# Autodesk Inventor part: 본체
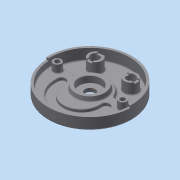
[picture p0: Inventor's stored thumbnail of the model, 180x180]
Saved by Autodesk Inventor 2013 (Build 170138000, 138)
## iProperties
Created: 2015-04
Part Number: 본체
Material: 일반
Document SubType Name: Modeling
Designer: Administrator
Density: 1 g/cm^3
Author: Administrator
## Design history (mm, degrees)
sketch "스케치1"
  geometry: C1 r 95 at (0, 0); 1 further point
  constraints: 1 centre point, 1 coincident
  dimensions: "d0" = 190 diameter of C1
extrude "돌출1" new body sketch "스케치1" distance "d1" = 32; taper "d2" = 0 deg
sketch "스케치2"
  geometry: C1 r 95 at (0, 0) reference; C2 r 90 at (0, 0)
  constraints: 1 centre point, 1 coincident
  dimensions: "d3" = 180 diameter of C2
extrude "돌출2" cut sketch "스케치2" distance "d4" = 25; taper "d5" = 0 deg
sketch "스케치3"
  geometry: L1 (-101.472, 0)-(101.472, 0); L2 (-94.916, -4)-(-89.929, -3.564); L3 (89.951, -2.955)-(94.939, -3.391); C1 r 90 at (0, 0) reference; A1 r 95 centre (0, 0) between (-95, 0) and (95, 0); A2 r 90 centre (0, 0) between (-90, 0) and (90, 0); 1 further point
  constraints: 8 point on circle, 6 end point, 4 point on line, 3 coincident, 2 centre point, 1 horizontal, 1 midpoint
  dimensions: "d6" = 5 deg angle of L2 L1; "d7" = 190 diameter of A1; "d8" = 180 diameter of A2; "d9" = 4.98634 horizontal distance of L2.start L2.end; "d10" = 5 deg angle of L1 L3; "d11" = 4.98797 horizontal distance of L3.start L3.end
extrude "돌출3" cut sketch "스케치3" distance "d12" = 5; taper "d13" = 0 deg
node "작업 평면1"
sketch "스케치9"
  geometry: C1 r 15 at (-40, 52); C2 r 15 at (40, 52); 1 further point
  constraints: 2 centre point, 1 horizontal alignment
  dimensions: "d77" = 30 diameter of C1; "d78" = 30 diameter of C2; "d79" = 80 distance of C2.centre C1.centre; "d80" = 40 horizontal distance of point (0, 0) C1.centre; "d81" = 52 vertical distance of point (0, 0) C1.centre
extrude "돌출7" join sketch "스케치9" stored distance "d82" = 25; taper "d83" = 0 deg
sketch "스케치10"
  geometry: C1 r 15 at (0, 0) reference; C2 r 15 at (80, 0) reference; C3 r 10 at (0, 0); C4 r 10 at (80, 0); 1 further point
  constraints: 2 centre point, 2 coincident
  dimensions: "d84" = 20 diameter of C3; "d85" = 20 diameter of C4
extrude "돌출8" cut sketch "스케치10" stored distance "d86" = 25; taper "d87" = 0 deg
sketch "스케치11"
  geometry: L1 (-6, 19.341)-(6, 19.341); L2 (6, 19.341)-(6, -18.609); L3 (6, -18.609)-(-6, -18.609); L4 (-6, -18.609)-(-6, 19.341); L5 (59.177, 6)-(102.733, 6); L6 (102.733, 6)-(102.733, -6); L7 (102.733, -6)-(59.177, -6); L8 (59.177, -6)-(59.177, 6); C1 r 10 at (0, 0) reference; C2 r 10 at (80, 0) reference; C3 r 15 at (80, 0) reference; 3 further points
  constraints: 16 end point, 4 parallel, 2 horizontal, 2 midpoint, 2 perpendicular, 1 horizontal alignment, 1 vertical alignment
  dimensions: "d88" = 12 distance of L1.start L1.end; "d90" = 12 distance of L7.end L5.start
extrude "돌출9" cut sketch "스케치11" distance "d92" = 3; taper "d93" = 0 deg
sketch "스케치12"
  geometry: L1 (-89.196, 12)-(-40.249, 12); L2 (40.249, 12)-(89.196, 12); A1 r 90 centre (0, 0) between (-89.196, 12) and (89.196, 12) reference; A2 r 42 centre (0, 0) between (40.249, 12) and (-40.249, 12); A3 r 90 centre (0, 0) between (-89.196, 12) and (89.196, 12)
  constraints: 6 point on circle, 4 end point, 2 centre point, 2 coincident, 2 horizontal, 1 horizontal alignment
  dimensions: "d98" = 12 distance from line of A1.centre L2; "d100" = 42 radius of A2
extrude "돌출10" join sketch "스케치12" distance "d101" = 7; taper "d102" = 0 deg
sketch "스케치13"
  geometry: A1 r 90 centre (0, 0) between (-89.196, 12) and (89.196, 12) reference; A2 r 59 centre (0, -19) between (-58.704, -13.1) and (58.704, -13.1); A3 r 41 centre (0, -19) between (-40.794, -14.9) and (40.794, -14.9); A4 r 9 centre (-49.749, -14) between (-40.794, -14.9) and (-58.704, -13.1); A5 r 9 centre (49.749, -14) between (58.704, -13.1) and (40.794, -14.9)
  constraints: 8 point on circle, 4 centre point, 2 tangent, 1 coincident, 1 horizontal alignment, 1 vertical alignment
  dimensions: "d103" = 118 diameter of A2; "d104" = 19 distance of A2.centre A1.centre; "d105" = 82 diameter of A3; "d106" = 18 diameter of A4; "d107" = 18 diameter of A5; "d108" = 5 vertical distance of A4.centre A3.centre
extrude "돌출11" cut sketch "스케치13" distance "d109" = 7; taper "d110" = 0 deg
sketch "스케치14"
  geometry: C1 r 9 at (-74, 0); C2 r 9 at (74, 0); A1 r 90 centre (0, 0) between (-89.196, 12) and (89.196, 12) reference
  constraints: 2 centre point, 2 horizontal alignment
  dimensions: "d111" = 18 diameter of C1; "d112" = 18 diameter of C2; "d113" = 148 distance of C2.centre C1.centre; "d114" = 74 distance of A1.centre C1.centre
extrude "돌출12" join sketch "스케치14" stored distance "d115" = 7; taper "d116" = 0 deg
sketch "스케치15"
  geometry: C1 r 9 at (-74, 0) reference; C2 r 9 at (74, 0) reference; 2 further points
  constraints: 2 coincident
hole "구멍5" sketch "스케치15" at (-74, 0), (74, 0) diameter "d117" = 11; stored, may be unused: countersink angle "d121" = 90 deg, drill point angle "d123" = 0 deg; dims "d118" = 6, "d119" = 18, "d120" = 11, "d122" = 11
sketch "스케치16"
  geometry: C1 r 35 at (0, 0); A1 r 42 centre (0, 0) between (40.249, 12) and (-40.249, 12) reference
  constraints: 1 centre point, 1 coincident
  dimensions: "d124" = 70 diameter of C1
extrude "돌출13" join sketch "스케치16" distance "d125" = 10; taper "d126" = -10 deg
hole "구멍6" diameter "d129" = 23; stored, may be unused: countersink angle "d133" = 90 deg, drill point angle "d135" = 0 deg; dims "d127" = 10, "d128" = 10, "d130" = 6, "d131" = 50, "d132" = 15, "d134" = 11
fillet "모깎기4" dims "d136" = 10
fillet "모깎기5" dims "d137" = 3, "d159" = 1
chamfer "모따기1" distance "d138" = 1; stored, may be unused: second distance "d139" = 2, angle "d140" = 45 deg
sketch "스케치17"
  geometry: L1 (-40, 0)-(43.953, 0); L2 (-36.062, -36.062)-(-52.326, -52.326); L3 (36.062, -36.062)-(52.326, -52.326); C1 r 12.5 at (0, 0) reference; A1 r 51 centre (0, 0) between (-36.062, -36.062) and (36.062, -36.062); A2 r 74 centre (0, 0) between (-52.326, -52.326) and (52.326, -52.326)
  constraints: 6 end point, 4 point on circle, 2 centre point, 2 coincident, 1 horizontal
  dimensions: "d141" = 102 diameter of A1; "d145" = 74 radius of A2; "d146" = 45 deg angle of L2 L1; "d147" = 45 deg angle of L3 L1; "d148" = 23 distance of L3.start L3.end; "d149" = 23 distance of L2.start L2.end
extrude "돌출14" join sketch "스케치17" distance "d150" = 5.5; taper "d151" = 0 deg
fillet "모깎기6" dims "d152" = 5
fillet "모깎기7" dims "d153" = 3
sketch "스케치18"
  geometry: C1 r 68 at (0, 0); A1 r 71 centre (0, 0) between (-46.435, -53.711) and (46.435, -53.711) reference
  constraints: 1 centre point, 1 coincident, 1 other
  dimensions: "d154" = 136 diameter of C1
feature "엠보싱1" sketch "스케치18" dims "d155" = 0.5, "d156" = 0
fillet "모깎기8" dims "d157" = 5
fillet "모깎기9" dims "d158" = 3
chamfer "모따기2" distance "d160" = 1; stored, may be unused: second distance "d161" = 2, angle "d162" = 45 deg
fillet "모깎기10" dims "d163" = 0.3
fillet "모깎기11" dims "d164" = 3
node "솔리드1"
node "투영된 루프1"
node "투영된 루프2"
other parameters: "d15" = 12, "d23" = 118, "d76" = 0, "d97" = 12, "d142" = 148, "d143" = 90 deg, "d144" = 45 deg
